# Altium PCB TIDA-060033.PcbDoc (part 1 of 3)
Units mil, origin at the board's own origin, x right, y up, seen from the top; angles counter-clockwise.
Board outline 1900 x 3360 mil, 8 copper layers (Top Layer L1, GND Plane L2, GND Plane L3, GND/Signal L4, GND Plane L5, GND Plane L6, GND Plane L7, Bottom Layer L8), stack 61.4 mil thick; 78 components, 27 nets, 146 pads, 1944 vias.
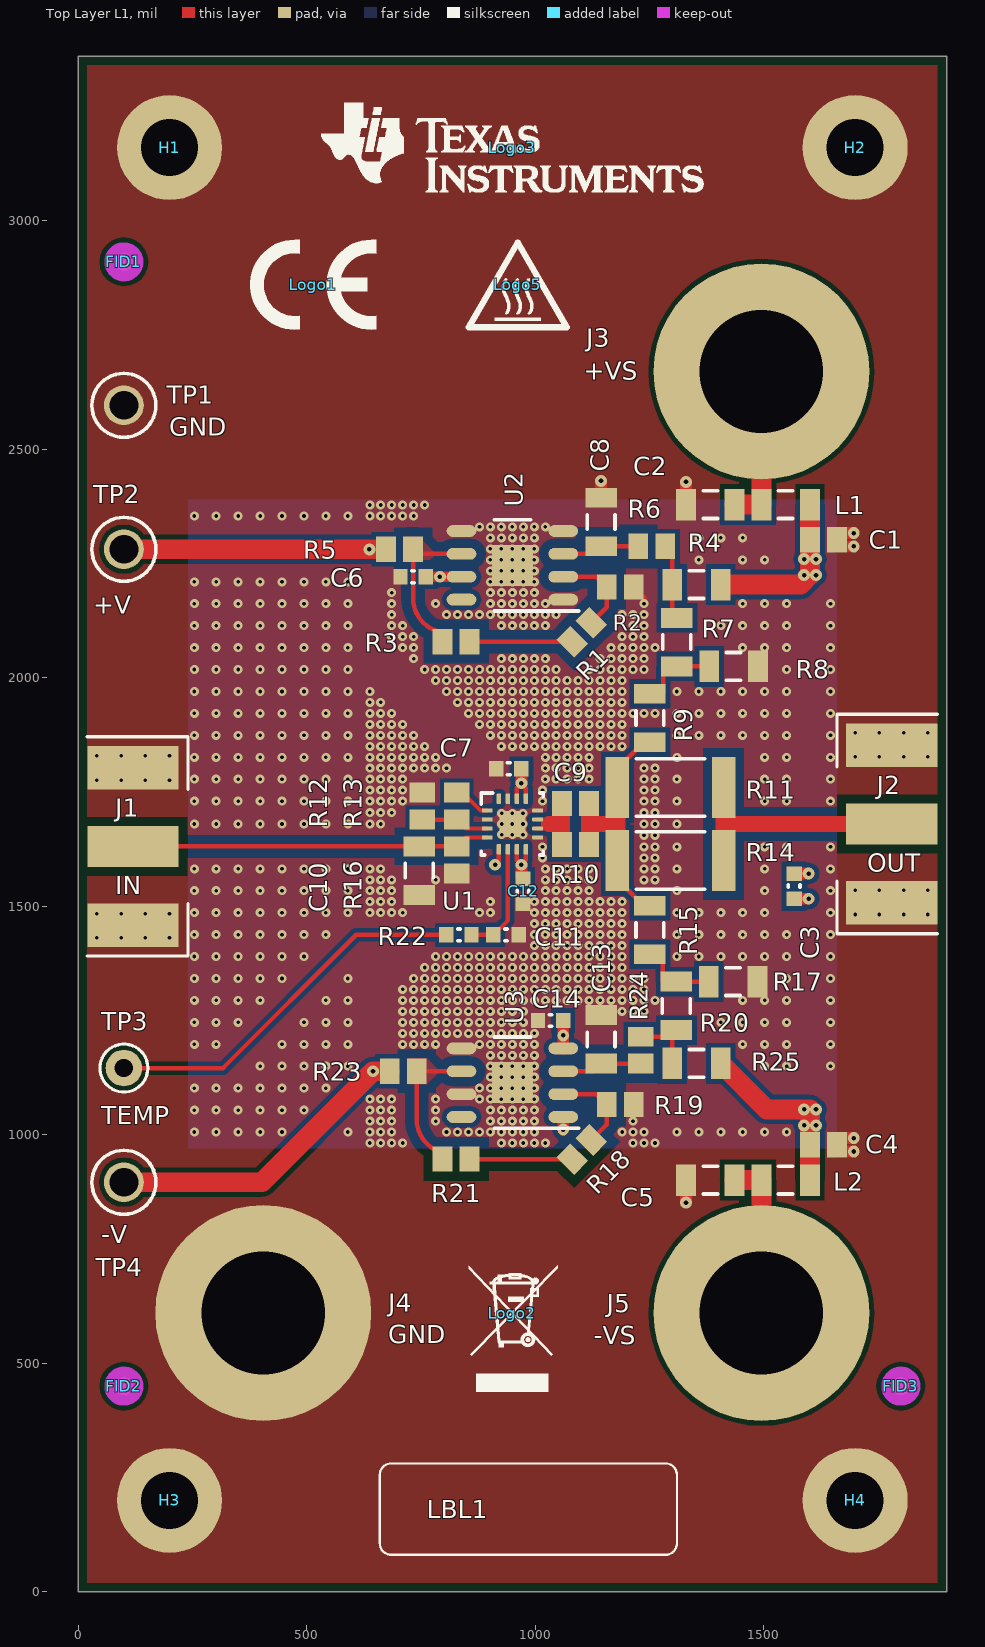
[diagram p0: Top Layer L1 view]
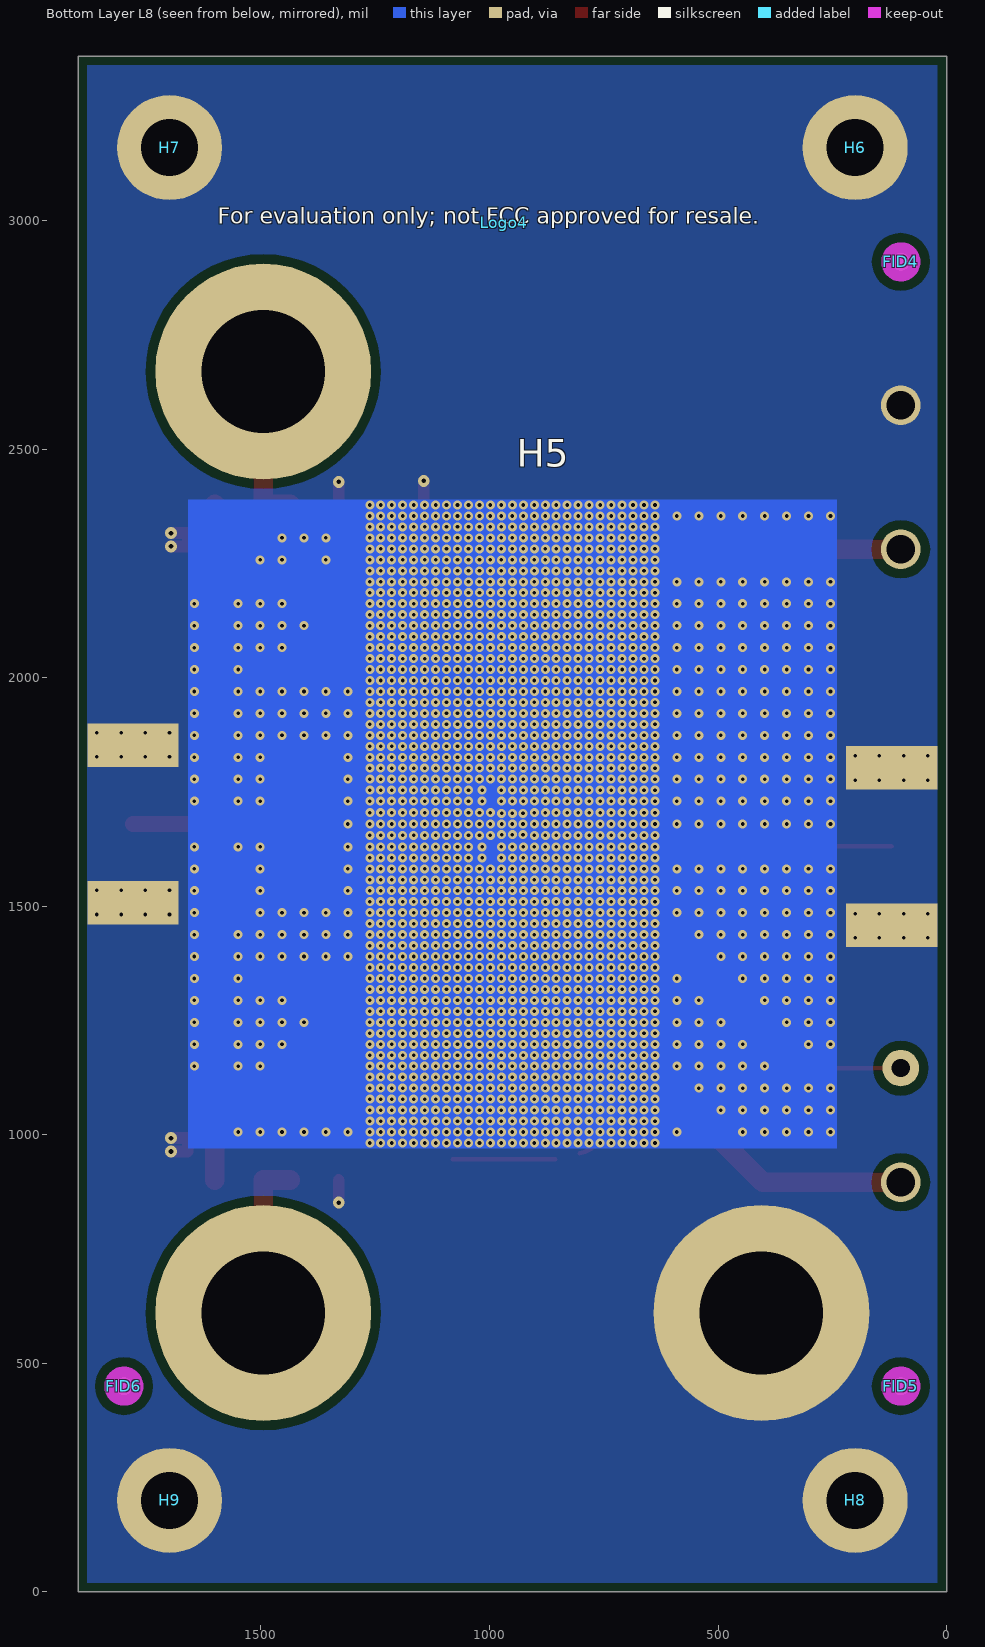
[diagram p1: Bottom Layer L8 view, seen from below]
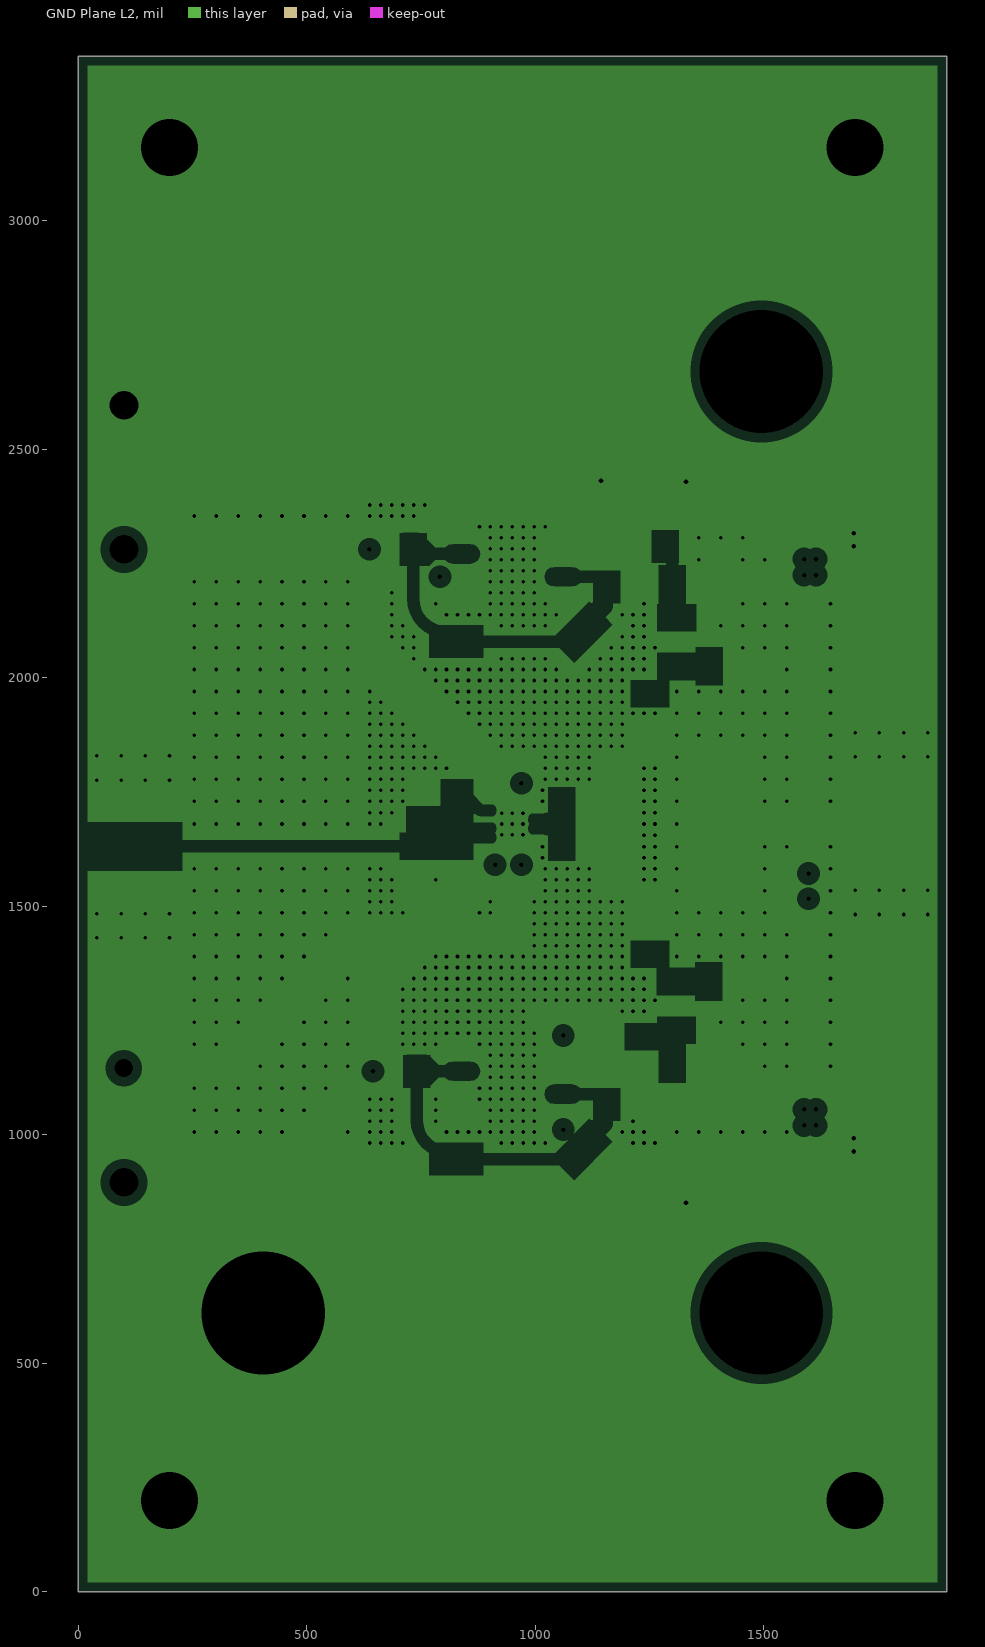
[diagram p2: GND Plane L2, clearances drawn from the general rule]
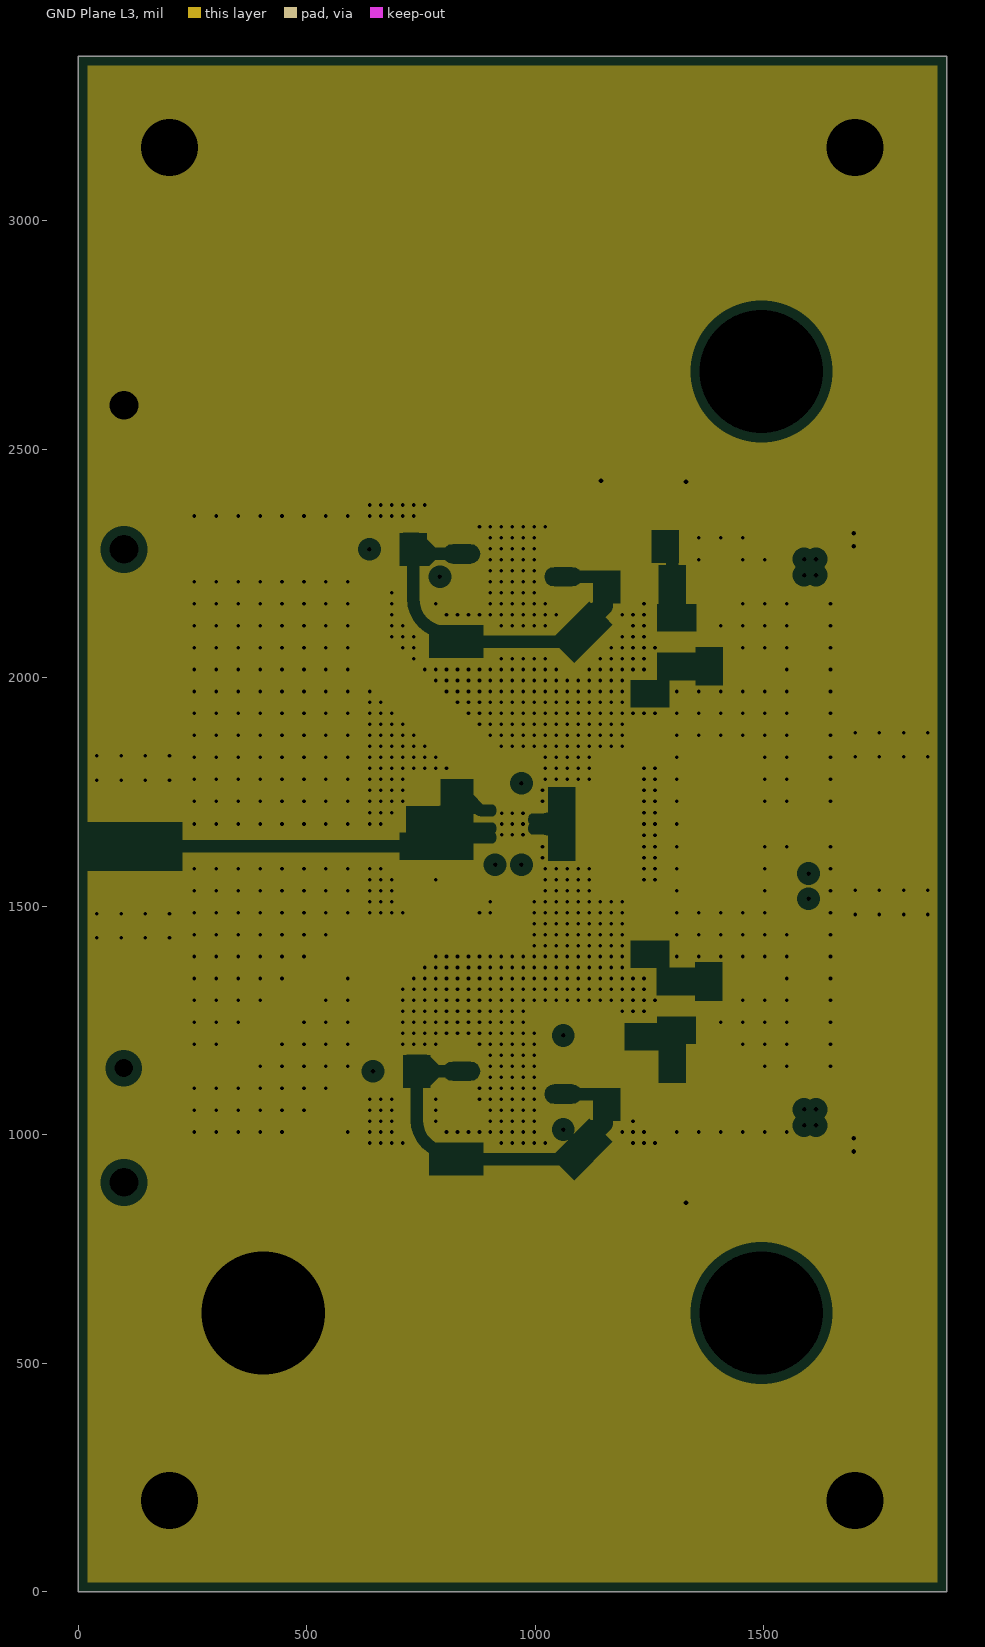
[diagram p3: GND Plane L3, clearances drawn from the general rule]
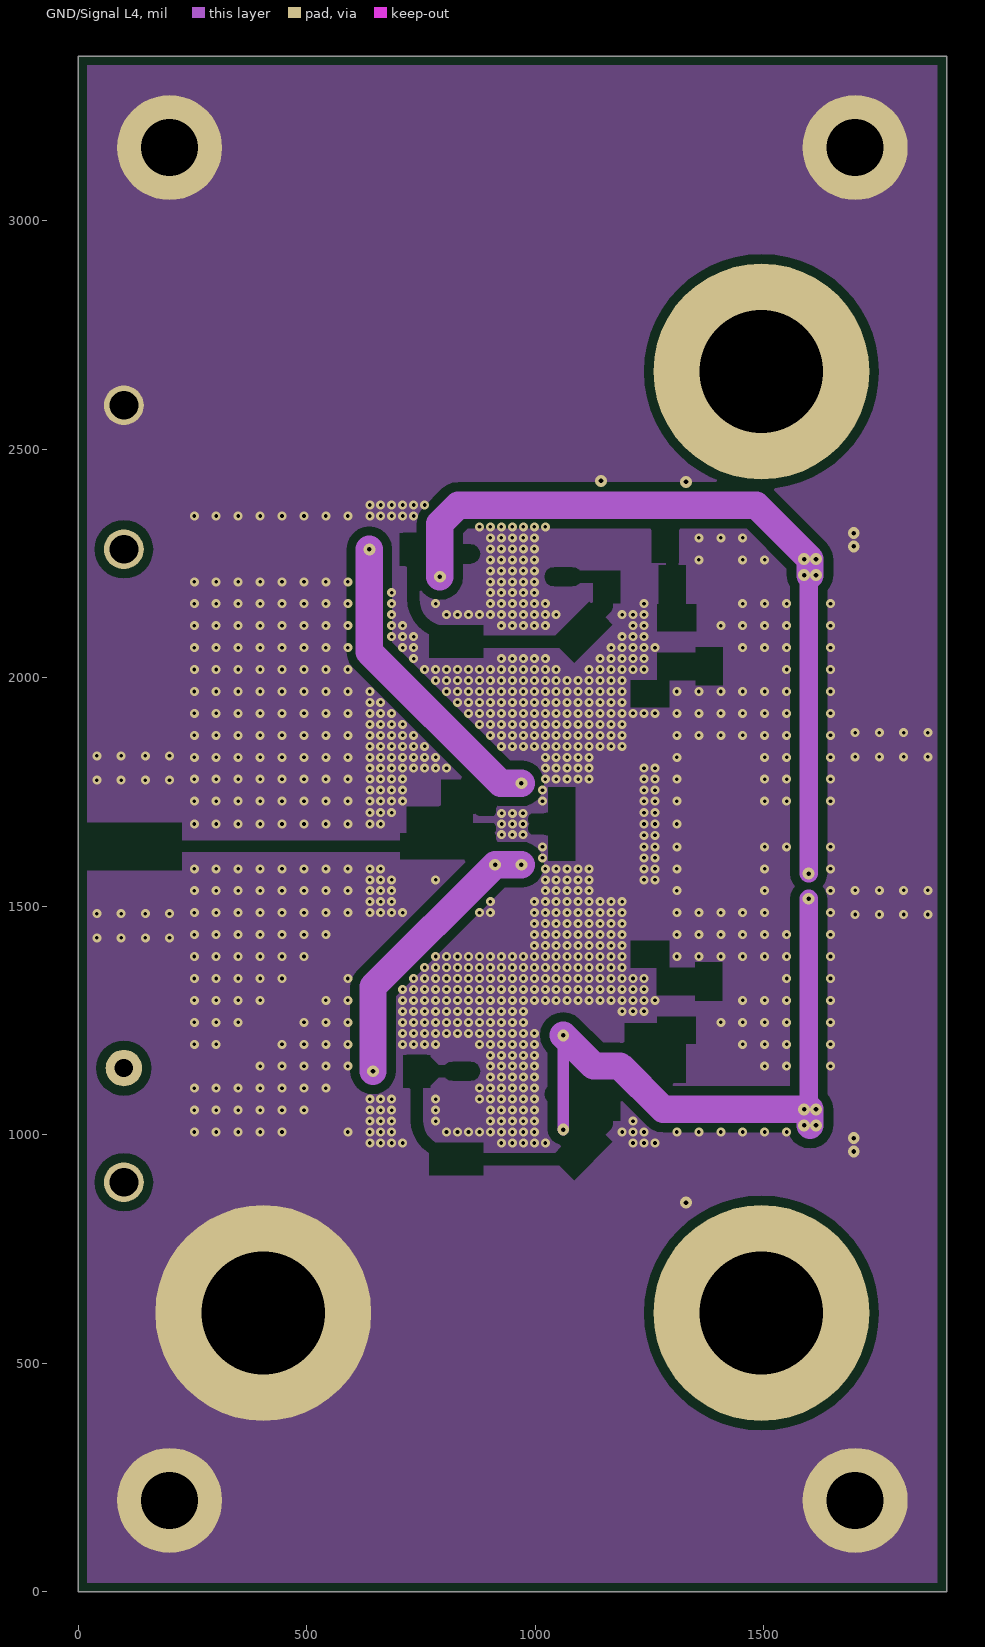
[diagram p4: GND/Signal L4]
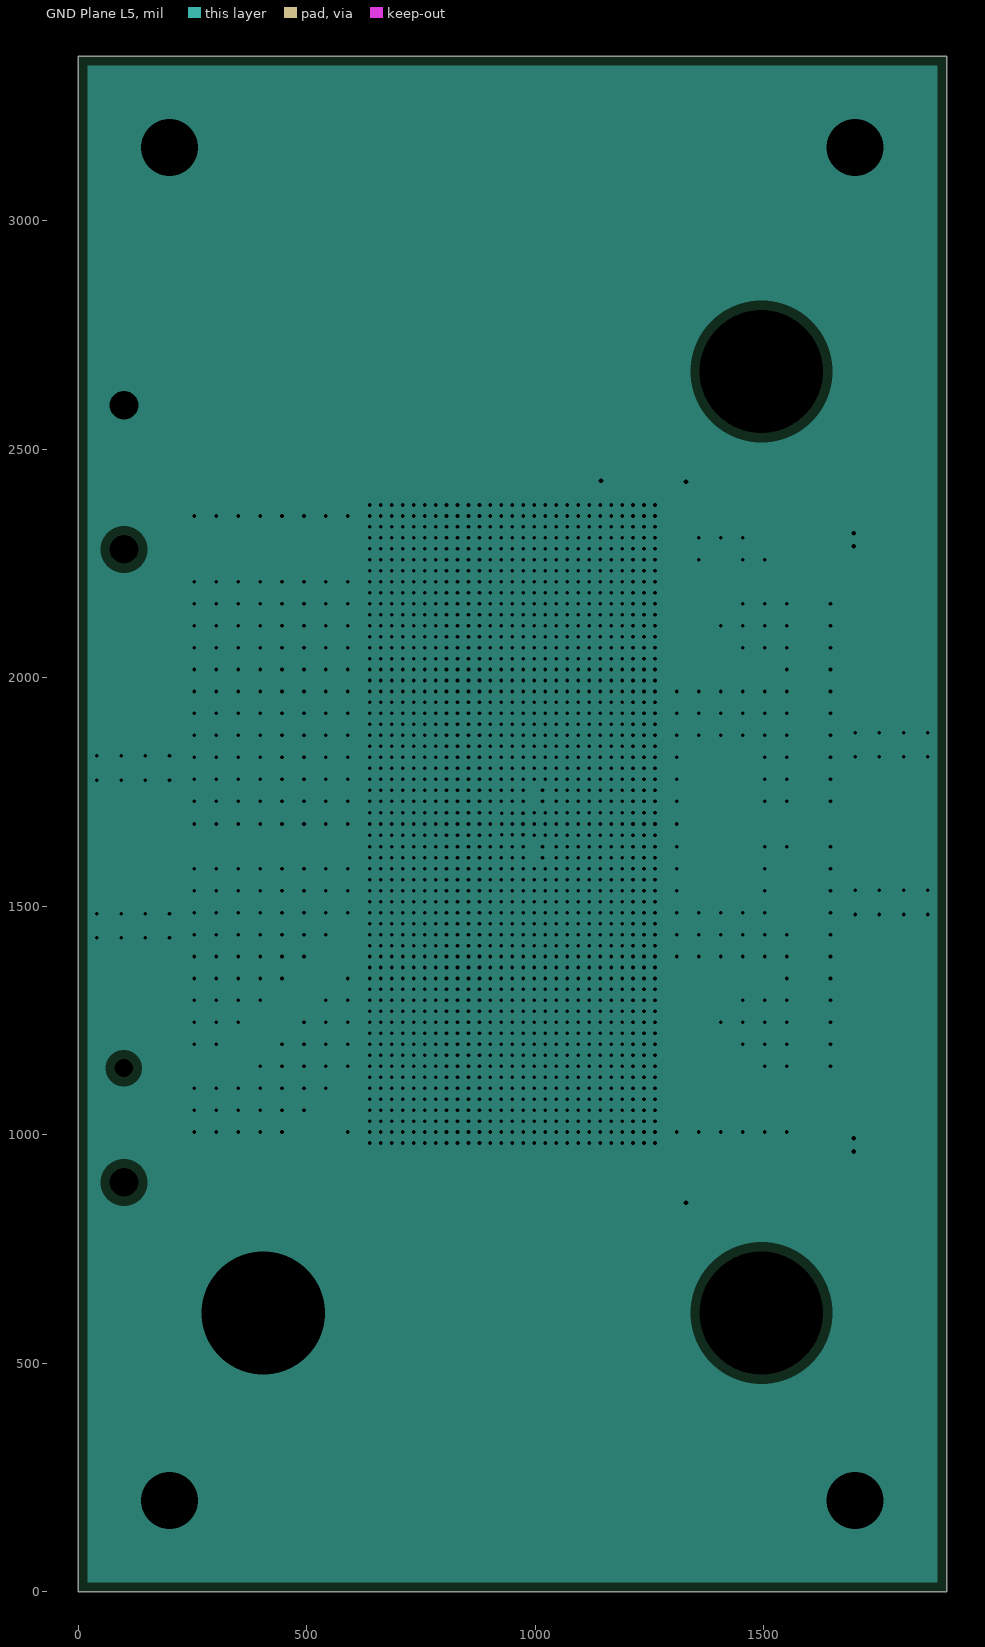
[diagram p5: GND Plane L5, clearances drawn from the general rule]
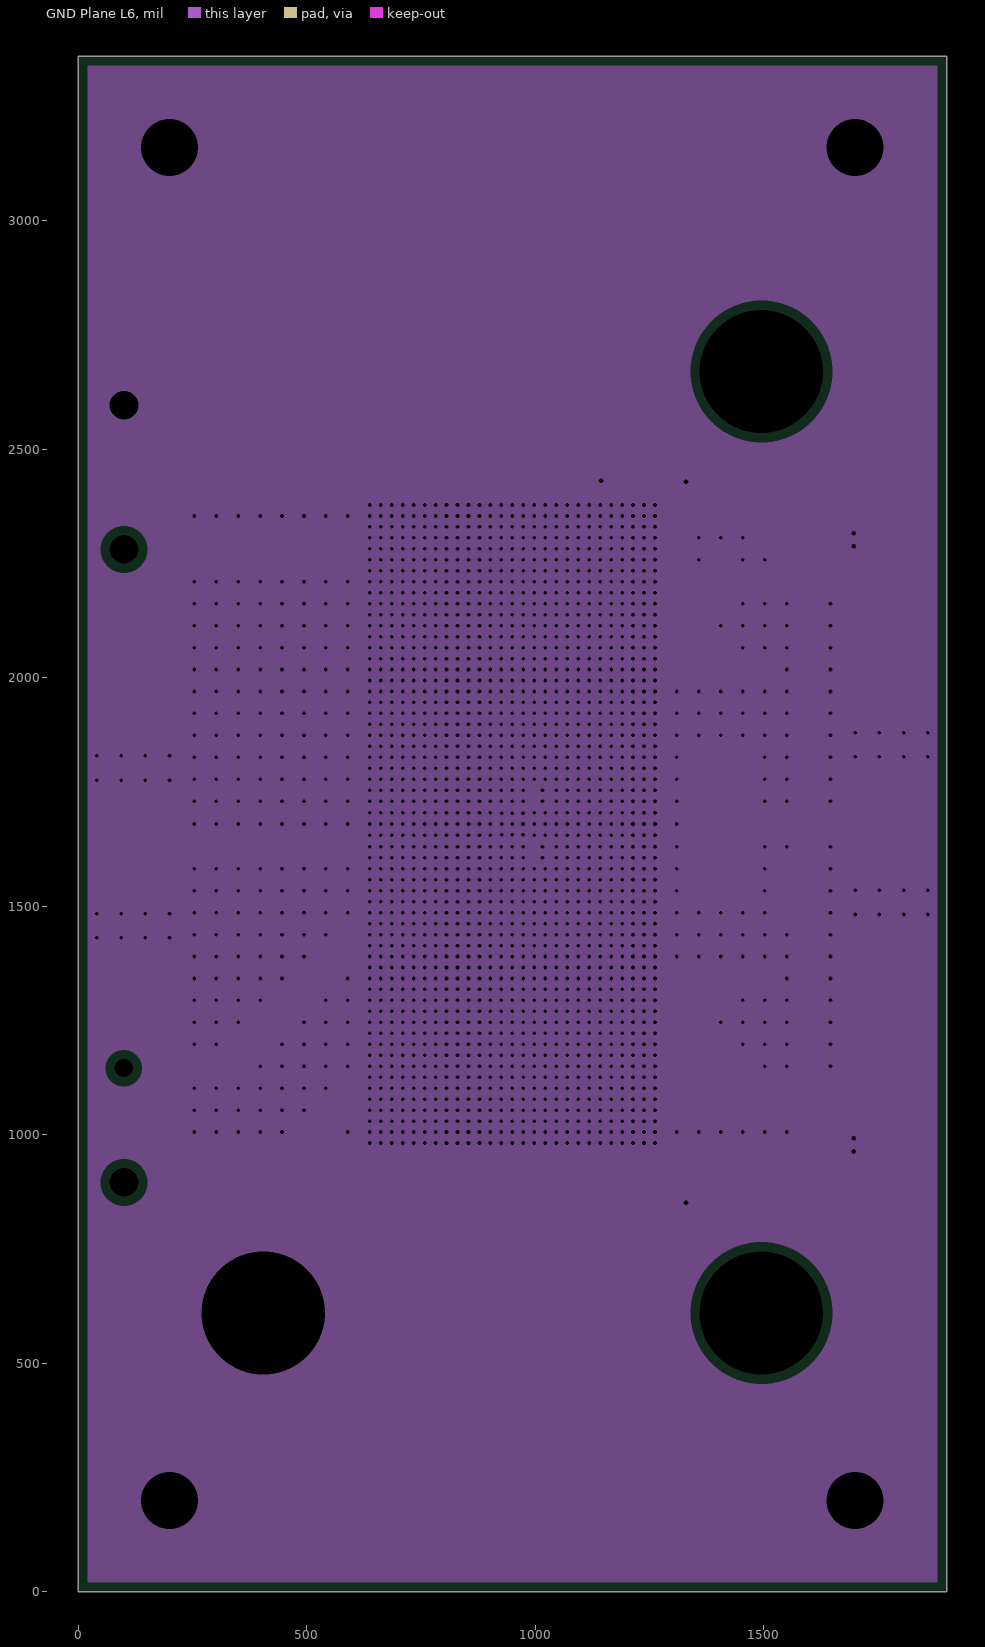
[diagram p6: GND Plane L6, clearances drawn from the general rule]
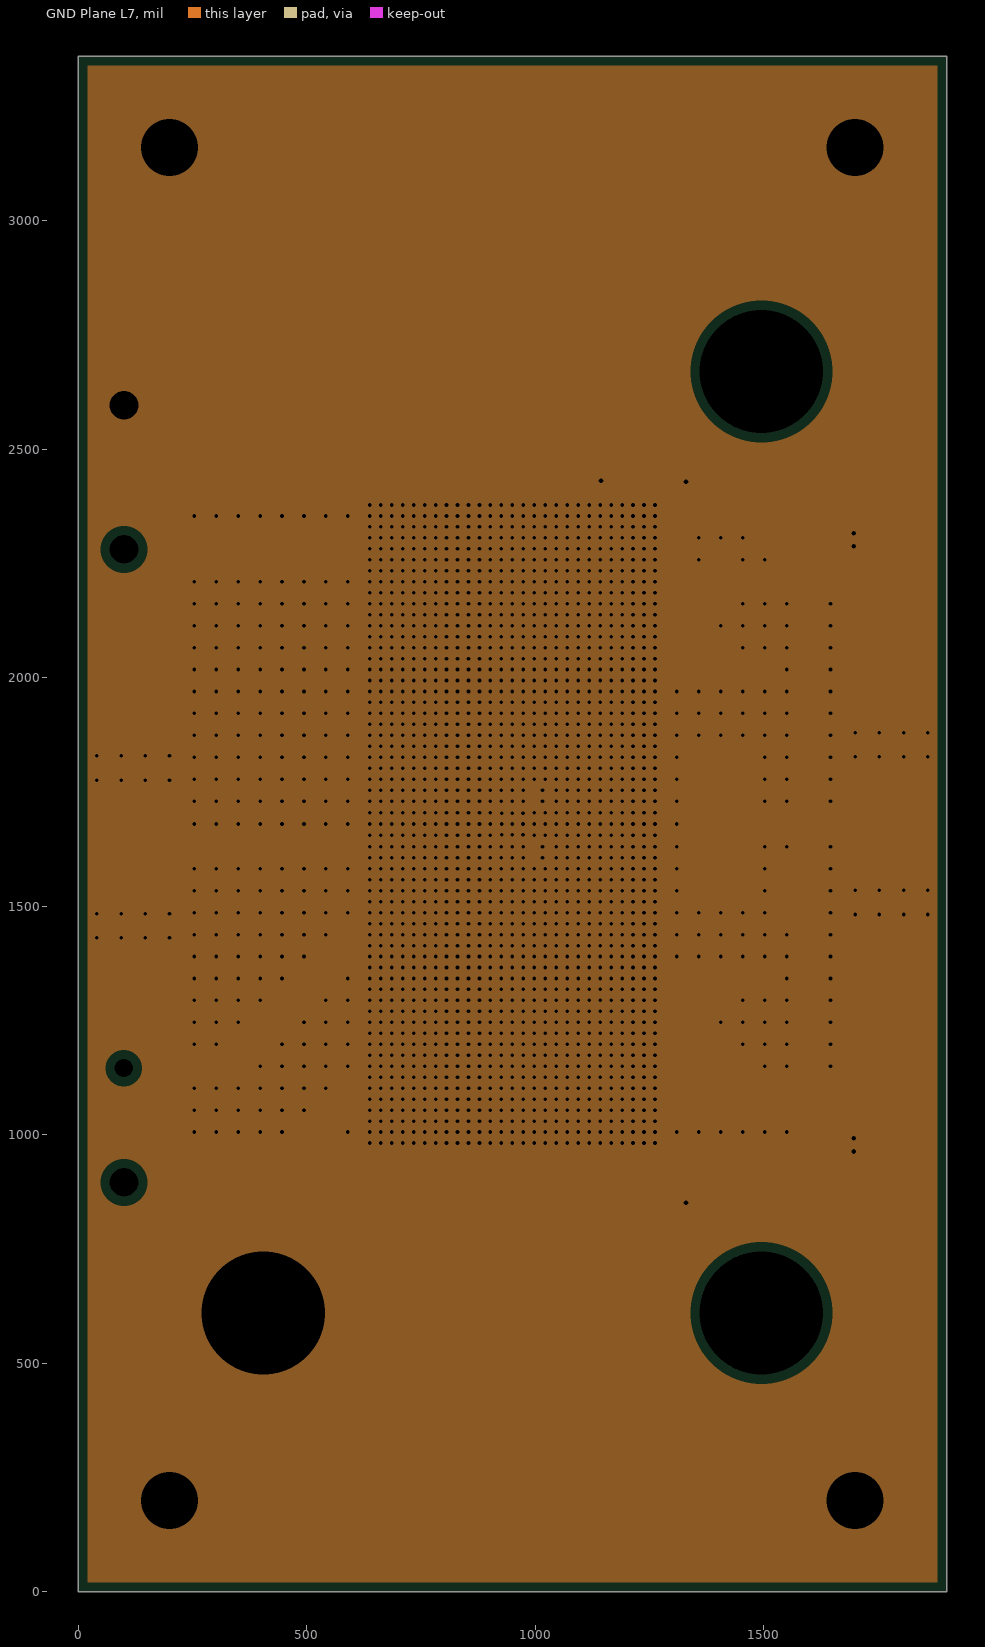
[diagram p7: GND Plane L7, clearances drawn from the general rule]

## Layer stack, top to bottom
Top Solder: solder mask 0.4, Solder Resist, Dk 3.5
Top Layer L1: signal copper 2.8
Dielectric 1: core 6, FR-4 High Tg, Dk 4.6
GND Plane L2: plane copper 2.8, net GND1
Dielectric 2: prepreg 6, FR-4 High Tg, Dk 4.6
GND Plane L3: plane copper 2.8, net GND1
Dielectric 3: prepreg 5, FR-4 High Tg, Dk 4.6
GND/Signal L4: signal copper 2.8
Dielectric 4: core 5, FR-4 High Tg, Dk 4.6
GND Plane L5: plane copper 2.8, net GND1
Dielectric 5: core 5, FR-4 High Tg, Dk 4.6
GND Plane L6: plane copper 2.8, net GND1
Dielectric 6: prepreg 6, FR-4 High Tg, Dk 4.6
GND Plane L7: plane copper 2.8, net GND1
Dielectric 7: core 6, FR-4 High Tg, Dk 4.6
Bottom Layer L8: signal copper 2.8
Bottom Solder: solder mask 0.4, Solder Resist, Dk 3.5

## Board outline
0,0 1900,0 1900,3360 0,3360

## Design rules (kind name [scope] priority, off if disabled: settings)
AcuteAngle [All] p1: minimum=4.50000000000000E+0001 checktracksonly=FALSE
AssemblyTestPointUsage [All] p1: valid=2
BoardOutlineClearance BoardOutlineClearance_MountingHoles [OnCopper and InComponentClass('Mounting Holes')] p1: gap=40 ignorepadtopadclearanceinfootprint=FALSE
BoardOutlineClearance BoardOutlineClearance_Poly [OnCopper and IsPoly] p2: gap=20 ignorepadtopadclearanceinfootprint=FALSE
BoardOutlineClearance [OnCopper and Not InComponentClass('Logo') and not InComponentClass('FiducialMark') and not InRegion(1000,500,4000,800) and not InPoly] p3: gap=20 ignorepadtopadclearanceinfootprint=FALSE
Clearance Clearance_FiducialMark [IsKeepOut and InComponentClass('FiducialMark') vs IsPad and InComponentClass('FiducialMark')] p1: gap=0 ignorepadtopadclearanceinfootprint=FALSE
Clearance Clearance_2 [(InNet('Netc16_1') OR InNet('Netc18_1') OR InNet('Netc19_1') OR InNet('Netc21_1') OR InNet('NetR1_2') OR InNet('NetR5_2') OR InNet('NetR17_2') OR InNet('NetJ4_1'))] p2: gap=20 ignorepadtopadclearanceinfootprint=FALSE except(0: Arc-Hole Track-Hole SMDPad-Hole THPad-Hole Via-Hole Fill-Hole Poly-Hole Region-Hole Text-Hole; 8: Text-Text; 9.05: Arc-SMDPad Track-SMDPad; 10: Arc-Arc Arc-Track Arc-Via Track-Track Track-Via SMDPad-SMDPad SMDPad-Via Fill-Fill Fill-Poly Fill-Region Poly-Poly Poly-Region Region-Region)
Clearance Clearance_3 [(InNet('NetC27_1') OR InNet('NetC30_2') OR InNet('NetC33_2') OR InNet('NetJ6_1') OR InNet('NetR25_1') OR InNet('NetR25_2') OR InNet('NetR26_1') OR InNet('NetR28_2') OR InNet('NetR29_1') OR InNet('NetR34_1') OR InNet('NetR34_2') OR InNet('NetR38_2') OR InNet('NetR43_1'))] p3: gap=20 ignorepadtopadclearanceinfootprint=FALSE except(0: Arc-THPad Arc-Hole Track-THPad Track-Hole SMDPad-Hole THPad-Hole Via-Hole Fill-Hole Poly-Hole Region-Hole Text-Hole; 6.81: Arc-SMDPad Track-SMDPad; 10: Arc-Arc Arc-Track Arc-Via Track-Track Track-Via SMDPad-SMDPad SMDPad-Via)
Clearance Clearance_1 [(InNamedPolygon('Top Layer L1-GND') OR (InNamedPolygon('Top Layer L1-GND1')))] p4: gap=10 ignorepadtopadclearanceinfootprint=FALSE except(0: Arc-Hole Track-Hole SMDPad-Hole THPad-Hole Via-Hole Fill-Hole Poly-Hole Region-Hole Text-Hole)
Clearance Clearance_Keepouts [((IsTrack Or IsArc) And Not InPoly) And IsFree and IsKeepOut vs ((IsTrack Or IsArc) And Not InPoly) And IsFree and IsKeepOut] p5: gap=0 ignorepadtopadclearanceinfootprint=FALSE
Clearance Clearance_Poly [InPolygon] p6: gap=20 ignorepadtopadclearanceinfootprint=FALSE except(0: Arc-Hole Track-Hole SMDPad-Hole THPad-Hole Via-Hole Fill-Hole Poly-Hole Region-Hole Text-Hole)
Clearance [All] p7: gap=5 ignorepadtopadclearanceinfootprint=FALSE except(0: Arc-Hole Track-Hole SMDPad-Hole THPad-Hole Via-Hole Fill-Hole Poly-Hole Region-Hole Text-Hole)
ComponentClearance ComponentClearance_MountingHoles_FiducialMarks [InComponentClass('Mounting Holes') vs InComponentClass('FiducialMark')] p1: gap=50 collisioncheckmode=3 verticalgap=10 showdistances=FALSE
ComponentClearance ComponentClearance_Shunt [InComponentClass('Header') vs InComponentClass('Shunt')] p2: gap=0 collisioncheckmode=3 verticalgap=0 showdistances=FALSE
ComponentClearance ComponentClearance_Logo [InComponentClass('Logo')] p3: gap=50 collisioncheckmode=3 verticalgap=10 showdistances=FALSE
ComponentClearance ComponentClearance_ScrewToNut [(HasFootprint('B_F_PMSSS4400025PH')) vs (HasFootprint('Keystone_2204'))] p4: gap=0 collisioncheckmode=3 verticalgap=0 showdistances=FALSE
ComponentClearance ComponentClearance_MountingHoles [InComponentClass('Mounting Holes')] p5: gap=250 collisioncheckmode=3 verticalgap=100000 showdistances=FALSE
ComponentClearance ComponentClearance_SmallPassives [HasFootprint('0201*') or HasFootprint('0402*') or HasFootprint('0508') or HasFootprint('0603*') or HasFootprint('0612') or HasFootprint('0805*') or HasFootprint('0815*') or HasFootprint('0830*') or HasFootprint('1206*') or HasFootprint('1210*') or HasFootprint('1808*') or HasFootprint('1812*') or HasFootprint('1825*') or HasFootprint('2010*') or HasFootprint('2220*') or HasFootprint('2225*') or HasFootprint('2512*') or HasFootprint('2728*') or HasFootprint('3518*') or HasFootprint('RGT0016A') or HasFootprint('DDA0008D*') vs HasFootprint('0201*') or HasFootprint('0402*') or HasFootprint('0508') or HasFootprint('0201*') or HasFootprint('0402*') or HasFootprint('0508') or HasFootprint('0603*') or HasFootprint('0612') or HasFootprint('0805*') or HasFootprint('0815*') or HasFootprint('0830*') or HasFootprint('1206*') or HasFootprint('1210*') or HasFootprint('1808*') or HasFootprint('1812*') or HasFootprint('1825*') or HasFootprint('2010*') or HasFootprint('2220*') or HasFootprint('2225*') or HasFootprint('2512*') or HasFootprint('2728*') or HasFootprint('3518*') or HasFootprint('RGT0016A') or HasFootprint('DDA0008D*')] p6: gap=10 collisioncheckmode=3 verticalgap=10 showdistances=FALSE
ComponentClearance ComponentClearance_THtoSMT [IsThruComponent vs IsSMTComponent] p7: gap=35 collisioncheckmode=3 verticalgap=30 showdistances=FALSE
ComponentClearance ComponentClearance_THtoTH [IsThruComponent vs IsThruComponent] p8: gap=30 collisioncheckmode=3 verticalgap=30 showdistances=FALSE
ComponentClearance [All] p9: gap=28 collisioncheckmode=3 verticalgap=10 showdistances=FALSE
DiffPairsRouting [All] p1: maxlimit=100 minlimit=10 mostfreqgap=10 toplayer_minwidth=15 toplayer_maxwidth=15 toplayer_prefwidth=15 midlayer1_minwidth=15 midlayer1_maxwidth=15 midlayer1_prefwidth=15 bottomlayer_minwidth=15 bottomlayer_maxwidth=15 bottomlayer_prefwidth=15 maxuncoupledlength=1000
FabricationTestPointUsage TestPointUsage [All] p1: valid=2 allowmultiple=FALSE
FabricationTestpoint Testpoint [All] p1: side=3 testpointundercomponent=TRUE minsize=40 maxsize=100 preferedsize=60 minholesize=0 maxholesize=40 preferedholesize=32 testpointgrid=1 allowsidetop=TRUE allowsidebottom=TRUE usegrid=TRUE gridtolerance=0.01
FanoutControl Fanout_LCC [IsLCC] p1: bgadir=Out bgaviamode=Centered fanoutstyle=Auto fanoutdirection=Alternating viagrid=1 // Fanout_LCC (Default Rule)
FanoutControl Fanout_BGA [IsBGA] p2: bgadir=Out bgaviamode=Centered fanoutstyle=Auto fanoutdirection=Alternating viagrid=1 // Fanout_BGA (Default Rule)
FanoutControl Fanout_Default [All] p4: bgadir=Out bgaviamode=Centered fanoutstyle=Auto fanoutdirection=Alternating viagrid=1 // Fanout_Default (Default Rule)
FanoutControl Fanout_Small [(CompPinCount < 5)] p5: bgadir=Out bgaviamode=Centered fanoutstyle=Auto fanoutdirection=OutThenIn viagrid=1 // Fanout_Small (Default Rule)
HoleSize [All] p1: absolutevalues=TRUE maxlimit=270 minlimit=7.87 maxpercent=80.000 minpercent=20.000
MinimumAnnularRing MinimumAnnularRing_1 [(InNamedUnion('Unions 9') or InNamedUnion('Unions 15') or InNamedUnion('Unions 28') or InNamedUnion('Unions 31') or InNamedUnion('Unions 34') or InNamedUnion('Unions 2154'))] p1: minimumring=5.91
MinimumAnnularRing MinimumAnnularRing_ThermalPadVias [IsVia and InAnyComponent] p2: minimumring=5.91
MinimumAnnularRing [All] p3: minimumring=7.5
MinimumSolderMaskSliver MinimumSolderMaskSliver_Logo [InComponentClass('Logo') vs InComponentClass('Logo')] p1: minsoldermaskwidth=0.7
MinimumSolderMaskSliver [All] p2: minsoldermaskwidth=3.94
PlaneClearance [All] p1: clearance=20
PlaneConnect [All] p1: planeconnectstyle=Direct reliefexpansion=10 reliefentries=4 reliefconductorwidth=10 reliefairgap=10
PolygonConnect [All] p1: connectstyle=Direct reliefconductorwidth=10 reliefentries=4 polygonreliefangle="90 Angle" airgapwidth=10
RoutingVias RoutingVias_1 [(InNamedUnion('Unions 9') or InNamedUnion('Unions 15') or InNamedUnion('Unions 28') or InNamedUnion('Unions 31') or InNamedUnion('Unions 34') or InNamedUnion('Unions 2154'))] p1: holewidth=28 width=50 viastyle="Through Hole" minholewidth=7.87 minwidth=19.68 maxholewidth=28 maxwidth=50
RoutingVias ThermalPadVias [IsVia and InAnyComponent] p2: holewidth=7.87 width=19.68 viastyle="Through Hole" minholewidth=7.87 minwidth=19.68 maxholewidth=12.99 maxwidth=23.62
RoutingVias [All] p3: holewidth=16 width=34 viastyle="Through Hole" minholewidth=7.87 minwidth=25 maxholewidth=40 maxwidth=65
SilkToBoardRegionClearance [Not ((IsComment or IsDesignator) And (Hide <> 'False')) and not InRegion(1000,500,4000,800)] p1:
SilkToSilkClearance SilkToSilkClearance_Pb-FreeLogo [(HasFootprint('Pb-Free_Overlay_Medium') OR HasFootprint('Pb-Free_Overlay_Small')) vs (HasFootprint('Pb-Free_Overlay_Medium') OR HasFootprint('Pb-Free_Overlay_Small'))] p1: silktosilkclearance=0
SilkToSilkClearance [All] p2: silktosilkclearance=4
SilkToSolderMaskClearance SilkToComponentPadClearance [(IsPad or IsFill or IsRegion) and InAnycomponent] p1: minsilkscreentomaskgap=5 clearancetoexposedcopper=TRUE
SilkToSolderMaskClearance "Silk to Solder Mask Opening" [All] p2: minsilkscreentomaskgap=4 clearancetoexposedcopper=FALSE
SolderMaskExpansion [All] p1: expansion=1.97
Width [All] p1: maxlimit=100 minlimit=6 preferedwidth=10 checkconnectedcopper=TRUE
14 further rules are at their usual default settings.

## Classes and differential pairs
component class Label: LBL1
component class AssemblyNote: ZZ1 ZZ2 ZZ3 ZZ4
component class FiducialMark: FID1 FID2 FID3 FID4 FID5 FID6
component class Logo: Logo3

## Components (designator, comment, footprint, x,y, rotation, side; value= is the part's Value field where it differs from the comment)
C1 "Capacitor" 0805L 1630.83,2302 r0 top value=1uF
C2 "GRT31CR61H106KE01L" 1206_180L 1383,2379 r180 top value=10uF
C3 "Capacitor" 0603L 1566.6,1544 r270 top value=0.01uF
C4 "Capacitor" 0805L 1630.83,978 r0 top value=1uF
C5 "GRT31CR61H106KE01L" 1206_180L 1383,901 r180 top value=10uF
C6 "C1608X5R1H104K080AA" 0603L 732.81,2221 r180 top value=0.1uF
C7 "C1608X5R1H104K080AA" 0603L 942.13,1800.79 r180 top value=0.1uF
C8 "GRM3195C2A102JA01D" 1206L 1144,2340.8 r270 top value=1000pF
C9 "GRM2165C1H102JA01D" 0805L 1088,1725.06 r0 top value=1000pF
C10 "12061A101JAT2A" 1206L 746.11,1577.82 r270 top value=100pF
C11 "C1608X5R1H104K080AA" 0603L 936.02,1437.41 r0 top value=0.1uF
C12 "C1608X5R1H104K080AA" 0603L 973.42,1532.63 r270 top value=0.1uF
C13 "GRM3195C2A102JA01D" 1206L 1144,1208.8 r270 top value=1000pF
C14 "C1608X5R1H104K080AA" 0603L 1033.66,1250 r180 top value=0.1uF
FID1 "Fiducial" Fiducial10-20 100,2910 r90 top
FID2 "Fiducial" Fiducial10-20 100,450 r90 top
FID3 "Fiducial" Fiducial10-20 1800,450 r90 top
FID4 "Fiducial" Fiducial10-20 100,2910 r90 bottom
FID5 "Fiducial" Fiducial10-20 100,450 r90 bottom
FID6 "Fiducial" Fiducial10-20 1800,450 r90 bottom
H1 "SCREW" B_F_PMSSS4400025PH 200,3160 r0 top
H2 "SCREW" B_F_PMSSS4400025PH 1700,3160 r0 top
H3 "SCREW" B_F_PMSSS4400025PH 200,200 r0 top
H4 "SCREW" B_F_PMSSS4400025PH 1700,200 r0 top
H5 "BDN14-3CB/A01" CTS_BDN14-3CB_A01 950,1680 r180 bottom locked
H6 "Nut" Keystone_2204 200,3160 r180 bottom
H7 "Nut" Keystone_2204 1700,3160 r180 bottom
H8 "Nut" Keystone_2204 200,200 r180 bottom
H9 "Nut" Keystone_2204 1700,200 r180 bottom
J1 "IN" Johnson_142-0701-80x_NoVias 120,1630.97 r90 top
J2 "OUT" Johnson_142-0701-80x_NoVias 1780,1680 r270 top
J3 "+VS" Keystone_6095 1495,2670 r0 top
J4 "GND" Keystone_6095 405,610 r0 top
J5 "-VS" Keystone_6095 1495,610 r0 top
L1 "Ferrite_Bead" 1206L 1548.15,2379 r0 top value="80 ohm"
L2 "Ferrite_Bead" 1206L 1548.15,901 r0 top value="80 ohm"
LBL1 "THT-14-423-10" Label_650x200 985,181 r0 top
Logo1 "CE Mark" CE_Mark_5mm 514,2860 r0 top
Logo2 "WEEE logo" WEEE_Minimum 950,610 r0 top
Logo3 "Texas Instruments" TI_Stacked_Overlay_Small 950,3160 r0 top
Logo4 "FCC disclaimer" FCC_disclaimer 968,2995 r180 bottom
Logo5 "CAUTION HOT SURFACE" IEC_HotSurface_Small 962,2860 r0 top
R1 "CRCW08052K10FKEA" 0805L 1101.69,2099.76 r45 top value=2.10k
R2 "CRCW08054K42FKEA" 0805L 1186,2198.44 r0 top value=4.42k
R3 "CRCW0805100RFKEA" 0805L 826.79,2078.89 r180 top value=100
R4 "CRCW12068K06FKEA" 1206L 1353,2204 r0 top value=8.06k
R5 "ERJ-6RQF3R9V" 0805L 703.28,2281 r0 top value=3.90
R6 "Resistor" 0805L 1255,2287.65 r180 top value=0
R7 "CRCW12062K00FKEA" 1206L 1309.9,2077.85 r90 top value=2.00k
R8 "CRCW12063K40FKEA" 1206L 1434,2024.7 r180 top value=3.40k
R9 "ERJ-8ENF6041V" 1206L 1251,1912 r90 top value=6.04k
R10 "Resistor" 0805L 1088,1634.94 r180 top value=0
R11 "CRCW2512100RFKEG" 2512 1296,1759.91 r180 top value=100
R12 "CRCW080554R9FKEA" 0805L 753,1719.18 r270 top value=54.9
R13 "CRCW0805499RFKEA" 0805L 828.5,1719.18 r90 top value=499
R14 "CRCW2512100RFKEG" 2512 1296,1600.09 r180 top value=100
R15 "ERJ-8ENF6041V" 1206L 1251,1448 r90 top value=6.04k
R16 "Resistor" 0805L 828.5,1601.45 r90 top value=49.9
R17 "CRCW12063K40FKEA" 1206L 1433,1335.3 r180 top value=3.40k
R18 "CRCW08052K10FKEA" 0805L 1101.69,967.76 r45 top value=2.10k
R19 "CRCW08054K42FKEA" 0805L 1186,1066.44 r0 top value=4.42k
R20 "CRCW12062K00FKEA" 1206L 1308.85,1282.15 r90 top value=2.00k
R21 "CRCW0805100RFKEA" 0805L 826.79,946.89 r180 top value=100
R22 "Resistor" 0603L 833,1437.41 r0 top value=0
R23 "ERJ-6RQF3R9V" 0805L 711.16,1139 r0 top value=3.90
R24 "Resistor" 0805L 1231,1185.18 r270 top value=0
R25 "CRCW12068K06FKEA" 1206L 1353,1156 r180 top value=8.06k
TP1 "GND" Keystone5011 100,2596 r0 top
TP2 "+V" Keystone5010 100,2281 r0 top
TP3 "TEMP" Keystone5000 100,1146 r90 top
TP4 "-V" Keystone5014 100,896 r0 top
U1 "THS3491IRGT" RGT0016A 950,1680 r0 top
U2 "THS3491IDDAR" DDA0008D_M 950,2246 r180 top
U3 "THS3491IDDAR" DDA0008D_M 950,1114 r180 top
ZZ1 "This Assembly Note is for PCB labels only" AssemblyNoteLabel 185,3898 r0 top
ZZ2 "These assemblies are ESD sensitive, ESD precautions shall be observed." AssemblyNote 185,3789.11 r0 top
ZZ3 "These assemblies must be clean and free from flux and all contaminants. Use of no clean flux is not acceptable." AssemblyNote 185,3700.56 r0 top
ZZ4 "These assemblies must comply with workmanship standards IPC-A-610 Class 2, unless otherwise specified." AssemblyNote 185,3612 r0 top

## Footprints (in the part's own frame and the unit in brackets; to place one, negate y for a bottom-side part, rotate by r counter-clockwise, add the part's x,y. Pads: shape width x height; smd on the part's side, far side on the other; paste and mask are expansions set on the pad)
0603L [mm] "0603 from SM-752 data"
  rect 0.8x0.85 smd: 1(-0.7,0) 2(0.7,0)
  silkscreen extent -0.07,-0.32 0.07,0.32, body extent -0.87,-0.47 0.87,0.47, height 1
0805L [mm] "0805 from SM-752 data"
  rect 1.1x1.4 smd: 1(-0.75,0) 2(0.75,0)
  body extent -1.1,-0.72 1.1,0.72, height 1.45
1206_180L [mm] "1206_180"
  rect 1.1x1.75 smd: 1(-1.35,0) 2(1.35,0)
  silkscreen extent -0.4,-0.78 0.4,0.77, body extent -1.75,-0.95 1.75,0.95, height 1.8
1206L [mm] "1206 from SM-752 data"
  rect 1.1x1.75 smd: 1(-1.35,0) 2(1.35,0)
  silkscreen extent -0.4,-0.77 0.4,0.77, body extent -1.7,-0.9 1.7,0.9, height 1.35
2512 [mm] "Chip Resistor, Body 6.3x3.2mm, IPC Medium Density"
  rect 1.3x3.4 smd: 1(-2.95,0) 2(2.95,0)
  silkscreen extent -1.9,-1.6 1.9,1.6, body extent -3.22,-1.67 3.22,1.67, height 0.71
AssemblyNote [mil] "Assembly Note"
AssemblyNoteLabel [mil] "Assembly Note for PCB Labels"
B_F_PMSSS4400025PH [mil] "MACHINE SCREW PAN PHILLIPS 4-40"
  round 230 hole 125: 1(0,0)
  body extent -109,-109 110,110, height 79
CE_Mark_5mm [mil] "Minimum text height for CE Mark"
  silkscreen extent -138,-98 138,98
CTS_BDN14-3CB_A01 [mil] "HEATSINK CPU W/ADHESIVE 1.41\"SQ"
  body extent -710,-710 710,710, height 370
DDA0008D_M [mm] "SOP, 8-Leads, Body 4.9x3.9mm, Pitch 1.27mm, Thermal Pad 2.28x2.28mm, IPC Low Density"
  rrect100% 1.65x0.65 smd: 1(-2.825,1.905) 2(-2.825,0.635) 3(-2.825,-0.635) 4(-2.825,-1.905) 5(2.825,-1.905) 6(2.825,-0.635) 7(2.825,0.635) 8(2.825,1.905)
  rrect4% 2.28x2.28 smd: 9(0,0)
  silkscreen extent -3.68,-2.54 1.02,2.54, body extent -3.01,-2.45 3.01,2.45, height 1.7
FCC_disclaimer [mil]
Fiducial10-20 [mm]
  round 1 smd mask+0.5: 1(0,0)
  Top Layer L1 keep-out circle w1.178: c0,0 r0.5
IEC_HotSurface_Small [mil]
  silkscreen extent -107,-93 107,92
Johnson_142-0701-80x_NoVias [mil] "Johnson Components recommended land pattern"
  rect 90x200 smd: 1(0,0)
  rect 95x200 smd: 2(-172.5,0) 3(172.5,0)
  rect 95x200 smd far side: 4(-172.5,0) 5(172.5,0)
  silkscreen extent -240,-120 240,100, body extent -190,-92 190,480, height 165
Keystone5000 [mil] "For Keystone 500x miniature loop terminals"
  round 80 hole 40: 1(0,0)
  silkscreen extent -52,-52 52,52, body extent -49,-49 49,49, height 182
Keystone5010 [mil] "Keystone Multipurpose loops"
  round 87 hole 63: 1(0,0)
  silkscreen extent -70,-70 70,70, body extent -63,-63 63,62, height 319
Keystone5011 [mil] "Keystone Multipurpose loops"
  round 87 hole 63: 1(0,0)
  silkscreen extent -70,-70 70,70, body extent -63,-63 63,62, height 319
Keystone5014 [mil] "Keystone Multipurpose loops"
  round 87 hole 63: 1(0,0)
  silkscreen extent -70,-70 70,70, body extent -63,-63 63,62, height 319
Keystone_2204 [mil] "HEX STANDOFF 4-40 ALUMINUM 3/4\""
  body extent -144,-125 144,125, height 750
Keystone_6095 [mm] "Banana Jack Uninsulated Standard Type"
  round 12 hole 6.858: 1(0,0)
  body extent -4.77,-5.5 4.75,5.49, height 2.39
Label_650x200 [mil] "Thermal Transfer Label"
  round 1 on Mech13: 0(0,0)
  silkscreen extent -325,-100 325,100, body extent -325,-100 325,100, height 1
RGT0016A [mm] "QFN, 16-Leads, Body 3x3mm, Pitch 0.5mm, Thermal Pad 1.45x1.45mm, TI Recommended"
  rrect42% 0.6x0.24 smd: 1(-1.4,0.75) 2(-1.4,0.25) 3(-1.4,-0.25) 4(-1.4,-0.75) 9(1.4,-0.75) 10(1.4,-0.25) 11(1.4,0.25) 12(1.4,0.75)
  rrect42% 0.24x0.6 smd: 5(-0.75,-1.4) 6(-0.25,-1.4) 7(0.25,-1.4) 8(0.75,-1.4) 13(0.75,1.4) 14(0.25,1.4) 15(-0.25,1.4) 16(-0.75,1.4)
  rrect7% 1.34x1.34 on Top Paste: 17(0,0)
  rrect7% 1.45x1.45 smd paste-0.725: 17(0,0)
  silkscreen extent -1.72,-1.73 1.72,1.73, body extent -1.5,-1.5 1.5,1.5, height 1
TI_Stacked_Overlay_Small [mil]
  silkscreen extent -418,-98 418,98
WEEE_Minimum [mil] "WEEElie bin"
  silkscreen extent -95,-172 99,104

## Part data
C1 C4: library part CMP-0007832-2, "CAP, CERM, 1 uF, 50 V, +/- 10%, X5R, 0805", Cap_Case=0805, Manufacturer=TDK, PartNumber=C2012X5R1H105K125AB, Supplier Part Number 1=445-7622-1-ND, TempCo=X5R, Tolerance_%=10%, Value1="0.008782 ohm", Value2=50V, ValueDisplayed=1uF
C2 C5: library part CMP-0009015-2, "CAP, CERM, 10 uF, 50 V, +/- 10%, X5R, AEC-Q200 Grade 1, 1206", Cap_Case=1206, Manufacturer=MuRata, Supplier Part Number 1=490-12456-1-ND, TempCo=X5R, Tolerance_%=10%, Value1=Unknown, Value2=50V, ValueDisplayed=10uF
C3: library part CMP-0006727-4, "CAP, CERM, 0.01 uF, 100 V, +/- 10%, X7R, 0603", Cap_Case=0603, Manufacturer=AVX, PartNumber=06031C103KAT2A, Supplier Part Number 1=478-1205-1-ND, TempCo=X7R, Tolerance_%=10%, Value1="0.098 ohm", Value2=100V, ValueDisplayed=0.01uF
C6 C7 C11 C12 C14: library part CMP-0007010-5, "CAP, CERM, 0.1 uF, 50 V, +/- 10%, X5R, 0603", Cap_Case=0603, Manufacturer=TDK, Supplier Part Number 1=445-7456-1-ND, TempCo=X5R, Tolerance_%=10%, Value1="0.0296 ohm", Value2=50V, ValueDisplayed=0.1uF
C8 C13: library part CMP-0008848-2, "CAP, CERM, 1000 pF, 100 V, +/- 5%, C0G/NP0, 1206", Cap_Case=1206, Manufacturer=MuRata, Supplier Part Number 1=490-3348-1-ND, TempCo=C0G/NP0, Tolerance_%=5%, Value1=Unknown, Value2=100V, ValueDisplayed=1000pF
C9: library part CMP-0008060-2, "CAP, CERM, 1000 pF, 50 V, +/- 5%, C0G/NP0, 0805", Cap_Case=0805, Manufacturer=MuRata, Supplier Part Number 1=490-1622-1-ND, TempCo=C0G/NP0, Tolerance_%=5%, Value1=Unknown, Value2=50V, ValueDisplayed=1000pF
C10: library part CMP-0008462-2, "CAP, CERM, 100 pF, 100 V, +/- 5%, C0G/NP0, 1206", Cap_Case=1206, Manufacturer=AVX, Supplier Part Number 1=478-1444-1-ND, TempCo=C0G/NP0, Tolerance_%=5%, Value1="0.701 ohm", Value2=100V, ValueDisplayed=100pF
FID1 FID2 FID3 FID4 FID5 FID6: library part CMP-0077181-1, "Fiducial mark.  There is nothing to buy or mount.", Manufacturer=N/A
H1 H2 H3 H4: library part CMP-0003715-1, "MACHINE SCREW PAN PHILLIPS 4-40", Manufacturer="B&F Fastener Supply", PartNumber="PMSSS 440 0025 PH", Supplier Part Number 1=H703-ND
H5: library part CMP-0079866-1, "HEATSINK CPU W/ADHESIVE 1.41\"SQ", Manufacturer="CTS Electrocomponents", Supplier Part Number 1=294-1101-ND
H6 H7 H8 H9: library part CMP-0003917-1, "HEX STANDOFF 4-40 ALUMINUM 3/4\"", Manufacturer=Keystone, PartNumber=2204, Supplier Part Number 1=36-2204-ND
J1 J2: library part CMP-0055821-1, "Connector, End launch SMA, 50 ohm, SMT", Manufacturer="Cinch Connectivity", PartNumber=142-0701-806, Supplier Part Number 1=J716-ND
J3 J4 J5: library part CMP-0055169-2, "Standard Banana Jack, Uninsulated", Manufacturer=Keystone, PartNumber=6095, Supplier Part Number 1=36-6095-ND
L1 L2: library part CMP-0003379-1, "Ferrite Bead, 80 ohm @ 100 MHz, 3 A, 1206", Manufacturer="Laird-Signal Integrity Products", PartNumber=HI1206N800R-10, Supplier Part Number 1=240-2409-1-ND, Value1="0.035 ohm", Value2=3A, ValueDisplayed="80 ohm"
LBL1: library part CMP-0003625-1, "Thermal Transfer Printable Labels, 0.650\" W x 0.200\" H - 10,000 per roll", Manufacturer=Brady, Supplier Part Number 1=97C5133
Logo1: library part CMP-0074844-1
Logo2: library part CMP-0074769-1
Logo3: library part CMP-0074838-1, "Texas Instrument Corporate Signature"
Logo4: library part CMP-0074847-1, "FCC_disclaimer"
Logo5: library part CMP-0074837-1, "IEC 61010-1 Hot Surface Warning"
R1 R18: library part CMP-0021108-3, "RES, 2.10 k, 1%, 0.125 W, AEC-Q200 Grade 0, 0805", Manufacturer=Vishay-Dale, Power_W=125mW, Supplier Part Number 1=541-2.10KCCT-ND, TempCo="100 ppm/C", Tolerance_%=1%, Value2=0.125W, Value_Code=2k10, ValueDisplayed=2.10k
R2 R19: library part CMP-0021289-3, "RES, 4.42 k, 1%, 0.125 W, AEC-Q200 Grade 0, 0805", Manufacturer=Vishay-Dale, Power_W=125mW, Supplier Part Number 1=541-4.42KCCT-ND, TempCo="100 ppm/C", Tolerance_%=1%, Value2=0.125W, Value_Code=4k42, ValueDisplayed=4.42k
R3 R21: "RES, 100, 1%, 0.125 W, 0805", Manufacturer=Vishay-Dale, Power_W=0.125, Supplier Part Number 1=541-100CCT-ND, TempCo="100 ppm/C", Tolerance_%=1, Value1=1%, Value2=0.125W, Value_Code=100R, ValueDisplayed=100
R4 R25: library part CMP-0017203-3, "RES, 8.06 k, 1%, 0.25 W, AEC-Q200 Grade 0, 1206", Manufacturer=Vishay-Dale, Power_W=250mW, Supplier Part Number 1=541-8.06KFCT-ND, TempCo="100 ppm/C", Tolerance_%=1%, Value2=0.25W, Value_Code=8k06, ValueDisplayed=8.06k
R5 R23: library part CMP-0021831-3, "RES, 3.90, 1%, 0.125 W, AEC-Q200 Grade 0, 0805", Manufacturer=Panasonic, Power_W=125mW, Supplier Part Number 1=P3.9DCT-ND, TempCo="200 ppm/C", Tolerance_%=1%, Value2=0.125W, Value_Code=3R90, ValueDisplayed=3.90
R6 R10 R24: library part CMP-0020442-3, "RES, 0, 5%, 0.125 W, AEC-Q200 Grade 0, 0805", Manufacturer=Vishay-Dale, PartNumber=CRCW08050000Z0EA, Power_W=125mW, Supplier Part Number 1=541-0.0ACT-ND, TempCo="200 ppm/C", Tolerance_%=5%, Value2=0.125W, Value_Code=0000, ValueDisplayed=0
R7 R20: library part CMP-0016844-3, "RES, 2.00 k, 1%, 0.25 W, AEC-Q200 Grade 0, 1206", Manufacturer=Vishay-Dale, Power_W=250mW, Supplier Part Number 1=541-2.00KFCT-ND, TempCo="100 ppm/C", Tolerance_%=1%, Value2=0.25W, Value_Code=2k00, ValueDisplayed=2.00k
R8 R17: library part CMP-0016948-3, "RES, 3.40 k, 1%, 0.25 W, AEC-Q200 Grade 0, 1206", Manufacturer=Vishay-Dale, Power_W=250mW, Supplier Part Number 1=541-3.40KFCT-ND, TempCo="100 ppm/C", Tolerance_%=1%, Value2=0.25W, Value_Code=3k40, ValueDisplayed=3.40k
R9 R15: library part CMP-0017669-3, "RES, 6.04 k, 1%, 0.25 W, AEC-Q200 Grade 0, 1206", Manufacturer=Panasonic, Power_W=250mW, Supplier Part Number 1=P6.04KFCT-ND, TempCo="100 ppm/C", Tolerance_%=1%, Value2=0.25W, Value_Code=6k04, ValueDisplayed=6.04k
R11 R14: library part CMP-0015428-3, "RES, 100, 1%, 1 W, AEC-Q200 Grade 0, 2512", Manufacturer=Vishay-Dale, Power_W=1W, Supplier Part Number 1=541-100AFCT-ND, TempCo="100 ppm/C", Tolerance_%=1%, Value_Code=100R, ValueDisplayed=100
R12: library part CMP-0021331-2, "RES, 54.9, 1%, 0.125 W, 0805", Manufacturer=Vishay-Dale, Power_W=125mW, Supplier Part Number 1=541-54.9CCT-ND, TempCo="100 ppm/C", Tolerance_%=1%, Value2=0.125W, Value_Code=54R9, ValueDisplayed=54.9
R13: library part CMP-0021282-1, "RES, 499, 1%, 0.125 W, 0805", Manufacturer=Vishay-Dale, Power_W=125mW, Supplier Part Number 1=541-499CCT-ND, TempCo="100 ppm/C", Tolerance_%=1%, Value2=0.125W, Value_Code=499R, ValueDisplayed=499
R16: library part CMP-0021284-3, "RES, 49.9, 1%, 0.125 W, AEC-Q200 Grade 0, 0805", Manufacturer=Vishay-Dale, PartNumber=CRCW080549R9FKEA, Power_W=125mW, Supplier Part Number 1=541-49.9CCT-ND, TempCo="100 ppm/C", Tolerance_%=1%, Value2=0.125W, Value_Code=49R9, ValueDisplayed=49.9
R22: library part CMP-0025697-4, "RES, 0, 5%, 0.1 W, AEC-Q200 Grade 0, 0603", Manufacturer=Vishay-Dale, PartNumber=CRCW06030000Z0EA, Power_W=100mW, Supplier Part Number 1=541-0.0GCT-ND, TempCo="200 ppm/C", Tolerance_%=5%, Value2=0.1W, Value_Code=0000, ValueDisplayed=0
TP1: library part CMP-0055148-1, "Test Point, Multipurpose, Black, TH", Color=Black, Manufacturer=Keystone, PartNumber=5011, Supplier Part Number 1=36-5011-ND
TP2: library part CMP-0055147-1, "Test Point, Multipurpose, Red, TH", Color=Red, Manufacturer=Keystone, PartNumber=5010, Supplier Part Number 1=36-5010-ND
TP3: library part CMP-0055137-1, "Test Point, Miniature, Red, TH", Color=Red, Manufacturer=Keystone, PartNumber=5000, Supplier Part Number 1=36-5000-ND
TP4: library part CMP-0055151-1, "Test Point, Multipurpose, Yellow, TH", Color=Yellow, Manufacturer=Keystone, PartNumber=5014, Supplier Part Number 1=36-5014-ND
U1: library part CMP-0013744-3, "High Voltage, Low Distortion, Current-Feedback Amplifier, RGT0016A (VQFN-16)", Alternate Manufacturer="Texas Instruments"
U2 U3: library part CMP-0013263-2, "900MHz High Power Output Current Feedback Amplifier, DDA0008D (SOIC-8)", Alternate Manufacturer="Texas Instruments", Alternate PartNumber=THS3491IDDAT
ZZ1: library part CMP-0003616-3
ZZ2: library part CMP-0077236-1
ZZ3: library part CMP-0077237-1
ZZ4: library part CMP-0077238-1

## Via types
v1: diameter 19.68, hole 7.87, Top Layer L1 to Bottom Layer L8, tented both sides, 966 vias
v2: diameter 19.68, hole 7.87, GND Plane L5 to Bottom Layer L8, tented bottom, 941 vias
v3: diameter 19.68, hole 7.87, Top Layer L1 to Bottom Layer L8, 12 vias
v4: diameter 26, hole 10.01, Top Layer L1 to GND/Signal L4, tented both sides, 10 vias
v5: diameter 26, hole 10.01, Top Layer L1 to GND/Signal L4, tented top, 8 vias
v6: diameter 26, hole 10, Top Layer L1 to Bottom Layer L8, tented both sides, 7 vias

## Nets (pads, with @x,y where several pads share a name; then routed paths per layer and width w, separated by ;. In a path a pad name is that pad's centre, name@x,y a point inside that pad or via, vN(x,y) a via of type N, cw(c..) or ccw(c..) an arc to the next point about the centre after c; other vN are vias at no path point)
+VS: C1.1 C3.1 C6.1 L1.2 R4.2 U2.7 | length 2151.9
  Top Layer L1 w23.62: C6.1@760.37,2221 v5(791.33,2221) U2.7@838.78,2221 U2.7@842.72,2221
  Top Layer L1 w26: C3.1@1566.6,1571.56 v4(1598.3,1571.56)
  Top Layer L1 w43.31: R4.2@1406.15,2204 1580.84,2204 1601.3,2224.45 C1.1@1601.3,2302 L1.2@1601.3,2379
  GND/Signal L4 w40: v4(1598.3,1571.56) v4@1598.3,2224.45
  GND/Signal L4 w60: v5(791.33,2221) 791.33,2337.33 831.5,2377.5 1483.25,2377.5 1601.3,2259.45 v4@1601.3,2224.45
  other v4: 1588.3,2224.45 1614.3,2224.45 1588.3,2259.45 1614.3,2259.45
-VS: C3.2 C4.1 C14.1 L2.2 R25.1 U3.1 U3.4 | length 1821.1
  Top Layer L1 w26: v5(1061.22,1011.24) U3.1@1061.22,1039 ; U3.4@1061.22,1189 v5(1061.22,1217.53) C14.1@1061.22,1250 ; C3.2@1566.6,1516.44 v4(1598.3,1516.44)
  Top Layer L1 w43.31: R25.1@1406.15,1156 1506.6,1055.55 1601.3,1055.55 C4.1@1601.3,978 L2.2@1601.3,901
  GND/Signal L4 w26: v5(1061.22,1011.24) v5(1061.22,1217.53)
  GND/Signal L4 w40: v4@1598.3,1055.55 v4(1598.3,1516.44)
  GND/Signal L4 w60: v5(1061.22,1217.53) 1128.22,1150.53 1185.5,1150.53 1280.49,1055.55 v4(1588.3,1055.55) 1598.3,1055.55 1601.3,1055.55 v4@1601.3,1020.55
  other v4: 1588.3,1020.55 1614.3,1020.55 1614.3,1055.55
